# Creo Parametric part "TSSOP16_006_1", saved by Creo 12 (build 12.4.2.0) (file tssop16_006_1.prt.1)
Units: Custom; MM, KILOGRAM, SECS

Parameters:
  PTC_WM_ITERATION = "0"
  PTC_WM_VERSION = "-.0"
  PTC_WM_LIFECYCLE_STATE = "In Work"
  PTC_WM_LIFECYCLE = "MO_CADDocument"
  PTC_WM_CREATED_BY = "Maximilian Roepper (Z0017RMS: MO)"
  PTC_WM_CREATED_ON = "18-Sep-26 11:36:42 AM"
  PTC_WM_MODIFIED_BY = "Maximilian Roepper (Z0017RMS: MO)"
  PTC_WM_MODIFIED_ON = "18-Sep-26 11:36:46 AM"
  PDMLINKNUMBER = "PDM000071455103"
  PTC_WM_NAME = "tssop16_006_1.prt"
  PTC_WM_NUMBER = "PDM000071455103"

Other parameters: WEIGHT, WEIGHT_FACTOR, WEIGHT_ADD, _MASS_TEMP, _DIFF_TEMP, MC_ERRORS, SUPPLIER

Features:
  1. coordinate system
  2. datum plane "PRT_YZ"
  3. datum plane "PRT_XY"
  4. datum plane "PRT_XZ"
  5. coordinate system
  6. datum axis
  7. datum axis
  8. datum axis
  9. coordinate system
  10. imported feature

Other named items: PRT, SIEMENS_MO, DRW_VIEW_ORG, PRT_X, PRT_Y, PRT_Z, CS0, ROUGH_GROB

Layers: 00_STD_CSYS-KSYS, 01_STD_PLANES-EBENEN, 02_STD_AXES-ACHSEN, 03_STD_CSYS-KSYS, 24_IMPORT_FEAT-IMPORT_KE

Surfaces: 14 plane, 8 cylinder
